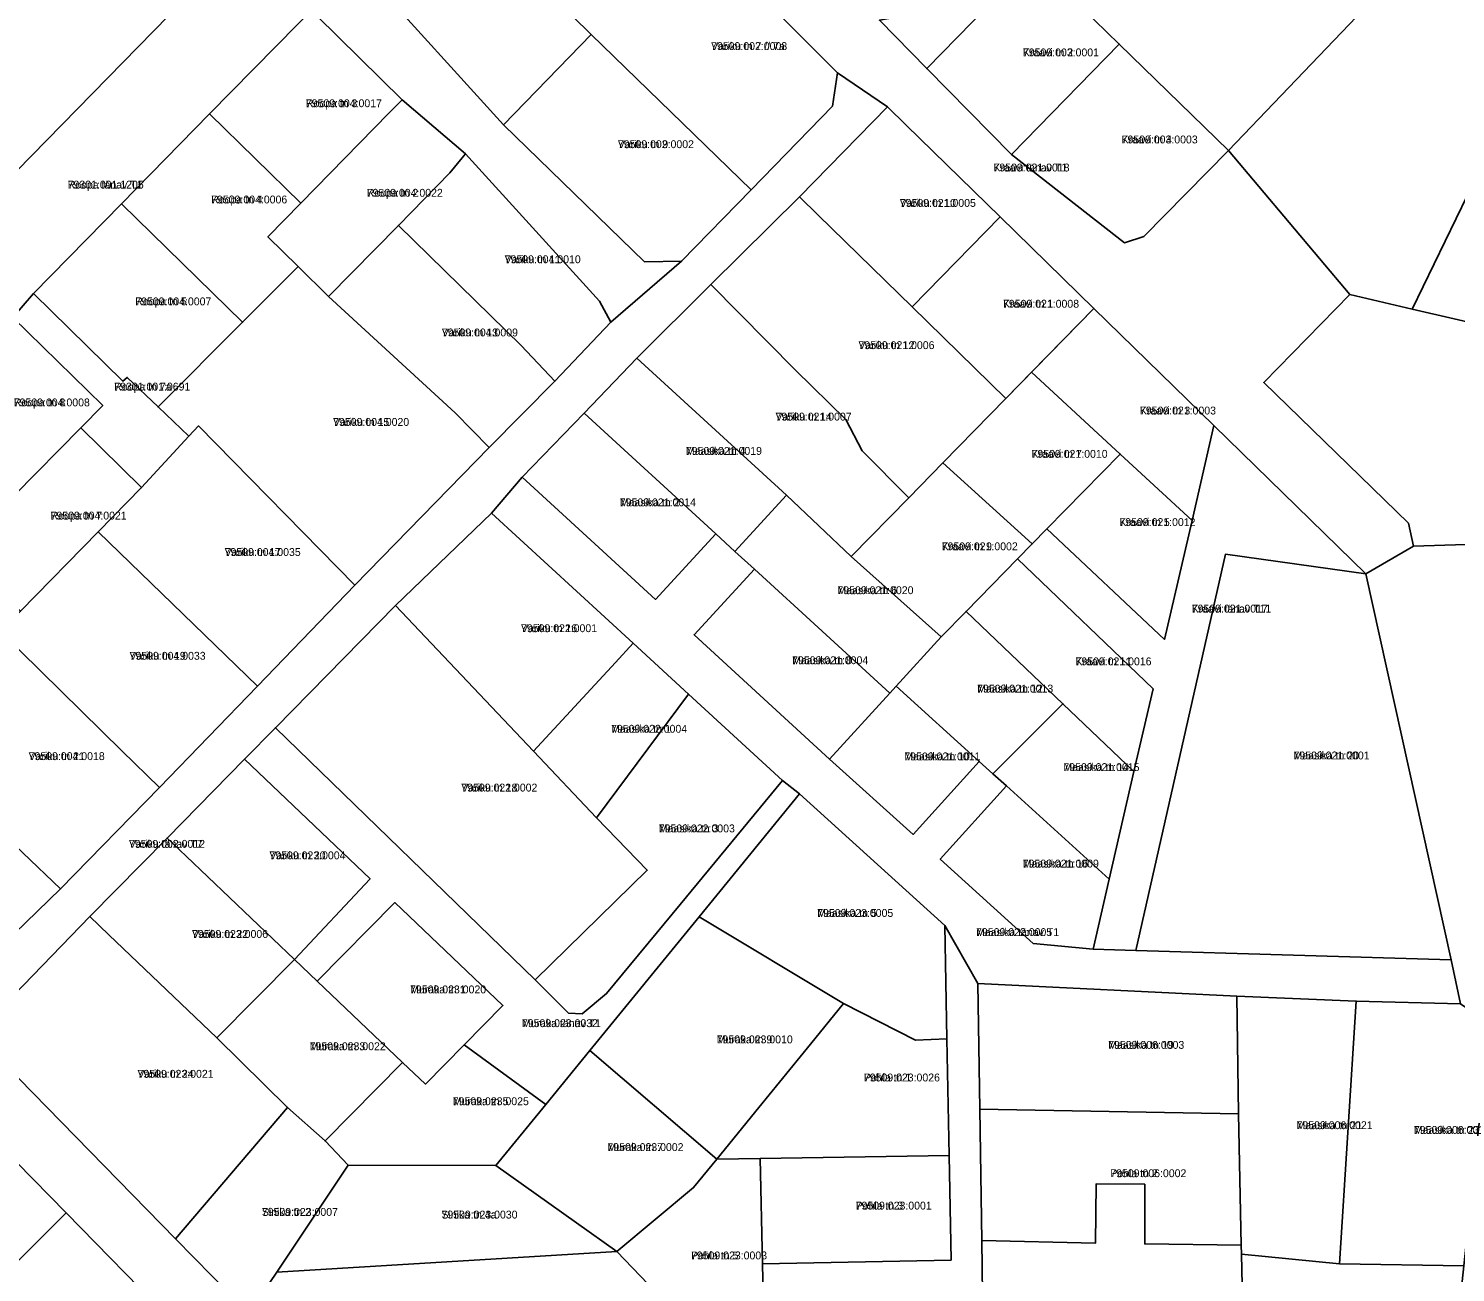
# Model space of a CAD drawing. Extents: x 643847 to 663718, y 6468443 to 6482775.
# Drawn here: x 658434.8 to 658706.9, y 6471070.1 to 6471307.4 of the extents above; entities that cross this region are included whole.
import ezdxf

# ---------------------------------------------------------------- set-up
doc = ezdxf.new("R2010")
doc.units = 0
for name, color, linetype in [('L_AADRESS', 7, 'Continuous'), ('PIIR', 7, 'Continuous'), ('TUNNUS', 7, 'Continuous')]:
    doc.layers.add(name, color=color, linetype=linetype)

msp = doc.modelspace()

# ---------------------------------------------------------------- linework, layer by layer
at = {"layer": 'PIIR'}
for points in [[(658667.9, 6471374.64), (658681.84, 6471388.98), (658712.74, 6471423.15), (658725.04, 6471439.2), (658731.9, 6471452.14), (658803.46, 6471462.91), (658790.44, 6471406.27), (658778.27, 6471410.06), (658762.02, 6471416.49), (658739.98, 6471437.01), (658717.62, 6471414.12), (658680.43, 6471376.08), (658675.68, 6471371.23), (658626.31, 6471320.49), (658606.07, 6471299.73), (658597.05, 6471308.95), (658605.51, 6471310.48), (658620.85, 6471326.25), (658641.07, 6471347.04), (658655.01, 6471361.37)], [(658642.77, 6471304.43), (658626.31, 6471320.49), (658675.68, 6471371.23), (658712.51, 6471335.21), (658663.59, 6471284.1)], [(658712.51, 6471335.21), (658721.8, 6471327.33), (658747.43, 6471319), (658760.36, 6471314.82), (658755.78, 6471292.14), (658727.03, 6471298.7), (658721.72, 6471301.39), (658698.63, 6471253.86), (658686.74, 6471256.66), (658663.59, 6471284.1)], [(658538.52, 6471309.73), (658542.11, 6471306.24), (658525.37, 6471289.04), (658499.62, 6471317.44), (658500.19, 6471323.31), (658512.72, 6471334.81)], [(658588.08, 6471292.56), (658572.57, 6471276.62), (658542.11, 6471306.24), (658538.52, 6471309.73), (658558.17, 6471329.93), (658569.12, 6471318.95), (658589.06, 6471298.96)], [(658626.31, 6471320.49), (658642.77, 6471304.43), (658622.25, 6471283.38), (658606.07, 6471299.73)], [(658705.68, 6471045.12), (658708.5, 6471071.36), (658713.16, 6471114.65), (658711.56, 6471118.9), (658707.89, 6471121.35), (658706.11, 6471129.75), (658689.82, 6471203.36), (658698.88, 6471208.62), (658734.86, 6471209.81), (658743.38, 6471243.53), (658755.78, 6471292.14), (658760.36, 6471314.82), (658765.5, 6471313.17), (658760.7, 6471290.4), (658727.38, 6471132.36), (658718.47, 6471080.15), (658713.7, 6471023.88), (658711.74, 6470952.85), (658701.04, 6470949.42), (658701.84, 6470983.89), (658702.59, 6471016.34)], [(658486.14, 6471308.22), (658487.58, 6471309.69), (658489.77, 6471309.81), (658506.03, 6471293.8), (658503.5, 6471291.21), (658486.71, 6471274.07), (658469.33, 6471291.09)], [(658559.33, 6471263), (658552.26, 6471262.91), (658525.37, 6471289.04), (658542.11, 6471306.24), (658572.57, 6471276.62)], [(658622.25, 6471283.38), (658642.77, 6471304.43), (658663.59, 6471284.1), (658647.49, 6471267.72), (658643.76, 6471266.51)], [(658721.72, 6471301.39), (658727.03, 6471298.7), (658755.78, 6471292.14), (658743.38, 6471243.53), (658698.63, 6471253.86)], [(658518.13, 6471283.46), (658517.5, 6471282.74), (658515.11, 6471279.84), (658505.32, 6471269.84), (658492.02, 6471256.27), (658486.24, 6471261.97), (658480.45, 6471267.68), (658486.71, 6471274.07), (658503.5, 6471291.21), (658506.03, 6471293.8)], [(658598.6, 6471292.43), (658602.17, 6471288.94), (658620.06, 6471271.46), (658603.28, 6471254.3), (658585.4, 6471271.77), (658581.82, 6471275.26)], [(658469.33, 6471291.09), (658486.71, 6471274.07), (658480.45, 6471267.68), (658486.24, 6471261.97), (658475.61, 6471251.35), (658452.52, 6471273.96)], [(658535.16, 6471240.11), (658528.72, 6471246.93), (658505.32, 6471269.84), (658515.11, 6471279.84), (658517.5, 6471282.74), (658518.13, 6471283.46), (658543.68, 6471255.36), (658545.86, 6471251.4)], [(658452.52, 6471273.96), (658475.61, 6471251.35), (658459.49, 6471235.22), (658453.62, 6471240.84), (658452.8, 6471240.1), (658435.71, 6471256.83)], [(658581.82, 6471275.26), (658585.4, 6471271.77), (658603.28, 6471254.3), (658621.17, 6471236.82), (658609.15, 6471224.52), (658602.64, 6471217.88), (658593.75, 6471226.84), (658590.64, 6471232.81), (658581.03, 6471242.22), (658564.93, 6471258.57)], [(658637.94, 6471253.99), (658621.17, 6471236.82), (658603.28, 6471254.3), (658620.06, 6471271.46)], [(658522.64, 6471227.49), (658516.12, 6471234.07), (658492.02, 6471256.27), (658505.32, 6471269.84), (658528.72, 6471246.93), (658535.16, 6471240.11)], [(658497.03, 6471201.22), (658467.19, 6471231.6), (658465.35, 6471229.61), (658459.49, 6471235.22), (658475.61, 6471251.35), (658486.24, 6471261.97), (658492.02, 6471256.27), (658516.12, 6471234.07), (658522.64, 6471227.49)], [(658435.71, 6471256.83), (658452.8, 6471240.1), (658453.62, 6471240.84), (658459.49, 6471235.22), (658465.35, 6471229.61), (658456.35, 6471219.83), (658444.74, 6471231.2), (658448.94, 6471235.48), (658431.78, 6471252.28)], [(658564.93, 6471258.57), (658581.03, 6471242.22), (658590.64, 6471232.81), (658593.75, 6471226.84), (658602.64, 6471217.88), (658591.67, 6471206.65), (658579.32, 6471218.35), (658550.79, 6471244.5)], [(658697.92, 6471213.01), (658670.35, 6471239.87), (658686.74, 6471256.66), (658698.64, 6471253.86), (658743.38, 6471243.53), (658734.86, 6471209.81), (658698.88, 6471208.62)], [(658660.83, 6471231.65), (658656.66, 6471213.56), (658642.98, 6471226.22), (658626.07, 6471241.84), (658637.94, 6471253.99)], [(658431.78, 6471252.28), (658448.94, 6471235.48), (658444.74, 6471231.2), (658432.14, 6471218.35), (658415, 6471235.13)], [(658569.51, 6471207.64), (658565.83, 6471211.02), (658540.75, 6471234.01), (658550.79, 6471244.5), (658579.32, 6471218.35)], [(658626.19, 6471209.07), (658609.15, 6471224.52), (658621.17, 6471236.82), (658626.07, 6471241.84), (658642.98, 6471226.22), (658628.99, 6471211.93)], [(658528.92, 6471221.81), (658540.75, 6471234.01), (658565.83, 6471211.02), (658554.34, 6471198.5)], [(658456.35, 6471219.83), (658448.07, 6471211.37), (658433.26, 6471196.25), (658421.65, 6471207.63), (658432.14, 6471218.35), (658444.74, 6471231.2)], [(658497.03, 6471201.22), (658478.44, 6471181.96), (658448.07, 6471211.37), (658456.35, 6471219.83), (658465.35, 6471229.61), (658467.19, 6471231.6)], [(658645.59, 6471165.65), (658649.23, 6471181.41), (658623.4, 6471206.21), (658626.19, 6471209.07), (658628.99, 6471211.93), (658651.41, 6471190.86), (658656.66, 6471213.56), (658660.83, 6471231.65), (658689.82, 6471203.36), (658663.07, 6471207.15), (658645.94, 6471131.56), (658637.78, 6471131.81), (658640.84, 6471145.11)], [(658623.4, 6471206.21), (658613.59, 6471196.21), (658608.82, 6471191.33), (658591.67, 6471206.65), (658602.64, 6471217.88), (658609.15, 6471224.52), (658626.19, 6471209.07)], [(658651.41, 6471190.86), (658628.99, 6471211.93), (658642.98, 6471226.22), (658656.66, 6471213.56)], [(658550.12, 6471190.14), (658523.09, 6471214.94), (658528.92, 6471221.81), (658554.34, 6471198.5), (658565.83, 6471211.02), (658569.51, 6471207.64), (658573.2, 6471204.28), (658561.72, 6471191.74), (658587.54, 6471168), (658603.47, 6471153.66), (658616.09, 6471167.59), (658618.68, 6471165.25), (658621.27, 6471162.91), (658608.64, 6471148.97), (658626.4, 6471132.88), (658637.78, 6471131.81), (658645.94, 6471131.56), (658706.11, 6471129.75), (658707.89, 6471121.35), (658687.99, 6471121.88), (658665.21, 6471122.79), (658615.84, 6471125.21), (658609.5, 6471136.29), (658581.8, 6471161.41), (658578.58, 6471163.98), (658560.67, 6471180.43)], [(658573.2, 6471204.28), (658569.51, 6471207.64), (658579.32, 6471218.35), (658591.67, 6471206.65), (658608.82, 6471191.33), (658600.25, 6471181.94), (658599.02, 6471180.64)], [(658523.09, 6471214.94), (658550.12, 6471190.14), (658546.73, 6471186.48), (658531.08, 6471169.56), (658504.78, 6471197.35)], [(658459.75, 6471162.61), (658452.61, 6471169.61), (658429.31, 6471192.43), (658433.26, 6471196.25), (658448.07, 6471211.37), (658478.44, 6471181.96)], [(658649.23, 6471181.41), (658645.59, 6471165.65), (658632.04, 6471178.59), (658613.59, 6471196.21), (658623.4, 6471206.21)], [(658645.94, 6471131.56), (658663.07, 6471207.15), (658689.82, 6471203.36), (658706.11, 6471129.75)], [(658561.72, 6471191.74), (658573.2, 6471204.28), (658599.02, 6471180.64), (658587.54, 6471168)], [(658504.78, 6471197.35), (658531.08, 6471169.56), (658543.09, 6471156.85), (658552.78, 6471146.83), (658531.38, 6471125.96), (658481.86, 6471174.01)], [(658616.09, 6471167.59), (658600.25, 6471181.94), (658608.82, 6471191.33), (658613.59, 6471196.21), (658632.04, 6471178.59), (658618.68, 6471165.25)], [(658440.9, 6471143.27), (658433.69, 6471150.16), (658410.17, 6471172.68), (658429.31, 6471192.43), (658452.61, 6471169.61), (658459.75, 6471162.61)], [(658560.67, 6471180.43), (658543.09, 6471156.85), (658531.08, 6471169.56), (658546.73, 6471186.48), (658550.12, 6471190.14)], [(658578.58, 6471163.98), (658559.08, 6471140.31), (658545.03, 6471123.31), (658540.35, 6471119.45), (658537.77, 6471119.57), (658531.38, 6471125.96), (658552.78, 6471146.83), (658543.09, 6471156.85), (658560.67, 6471180.43)], [(658587.54, 6471168), (658599.02, 6471180.64), (658600.25, 6471181.94), (658616.09, 6471167.59), (658603.47, 6471153.66)], [(658640.84, 6471145.11), (658621.27, 6471162.91), (658618.68, 6471165.25), (658632.04, 6471178.59), (658645.59, 6471165.65)], [(658416.27, 6471133.08), (658389.69, 6471159.47), (658406.6, 6471176.18), (658410.17, 6471172.68), (658433.69, 6471150.16), (658440.9, 6471143.27), (658423.21, 6471126.19)], [(658525.26, 6471121.01), (658504.63, 6471140.68), (658489.85, 6471125.7), (658485.5, 6471129.84), (658499.92, 6471145.18), (658475.97, 6471168.02), (658481.86, 6471174.01), (658531.38, 6471125.96), (658537.77, 6471119.57), (658540.35, 6471119.45), (658545.03, 6471123.31), (658559.08, 6471140.31), (658578.58, 6471163.98), (658581.8, 6471161.41), (658562.66, 6471137.96), (658541.82, 6471112.44), (658533.41, 6471102.13), (658517.88, 6471113.53)], [(658475.97, 6471168.02), (658499.92, 6471145.18), (658485.5, 6471129.84), (658464.87, 6471149.51), (658461.2, 6471152.98)], [(658609.5, 6471136.29), (658609.91, 6471114.69), (658603.92, 6471114.46), (658590.22, 6471121.4), (658562.66, 6471137.96), (658581.8, 6471161.41)], [(658626.4, 6471132.88), (658608.64, 6471148.97), (658621.27, 6471162.91), (658640.84, 6471145.11), (658637.78, 6471131.81)], [(658461.2, 6471152.98), (658464.87, 6471149.51), (658485.5, 6471129.84), (658470.72, 6471114.88), (658450.09, 6471134.54), (658446.47, 6471137.99)], [(658504.63, 6471140.68), (658525.26, 6471121.01), (658517.88, 6471113.53), (658510.48, 6471106.04), (658506.13, 6471110.18), (658489.85, 6471125.7)], [(658446.47, 6471137.99), (658450.09, 6471134.54), (658470.72, 6471114.88), (658484.2, 6471101.6), (658462.81, 6471076.54), (658424.66, 6471115.49)], [(658562.66, 6471137.96), (658590.22, 6471121.4), (658583.9, 6471113.65), (658574.04, 6471101.56), (658566.02, 6471091.72), (658541.82, 6471112.44)], [(658485.5, 6471129.84), (658489.85, 6471125.7), (658506.13, 6471110.18), (658491.33, 6471095.2), (658484.2, 6471101.6), (658470.72, 6471114.88)], [(658615.84, 6471125.21), (658665.21, 6471122.79), (658665.52, 6471100.35), (658616.19, 6471101.24)], [(658610.34, 6471092.46), (658574.29, 6471091.85), (658566.02, 6471091.72), (658574.04, 6471101.56), (658583.9, 6471113.65), (658590.22, 6471121.4), (658603.92, 6471114.46), (658609.91, 6471114.69)], [(658665.21, 6471122.79), (658687.99, 6471121.88), (658684.81, 6471071.8), (658666.09, 6471073.61), (658666.06, 6471075.36), (658665.52, 6471100.35)], [(658707.89, 6471121.35), (658711.56, 6471118.9), (658713.16, 6471114.65), (658708.5, 6471071.36), (658684.81, 6471071.8), (658687.99, 6471121.88)], [(658461.6, 6471061.42), (658441.96, 6471081.48), (658416.68, 6471107.25), (658424.66, 6471115.49), (658462.81, 6471076.54), (658476.83, 6471062.32), (658517.42, 6471018.28), (658559.1, 6470978.87), (658559.41, 6470962.42), (658559.54, 6470955.69), (658559.82, 6470941.57), (658546.56, 6470940.85), (658544.36, 6470976.37), (658531.54, 6470989.71), (658510.64, 6471011.43), (658468.62, 6471054.26), (658441.51, 6471027.68), (658414.39, 6471001.08), (658383.69, 6470970.97), (658376.94, 6470978.53), (658388.98, 6470990.32), (658401.04, 6471002.12), (658427.31, 6471027.85), (658444.46, 6471044.63)], [(658506.13, 6471110.18), (658510.48, 6471106.04), (658517.88, 6471113.53), (658533.41, 6471102.13), (658523.92, 6471090.52), (658495.76, 6471090.6), (658491.33, 6471095.2)], [(658533.41, 6471102.13), (658541.82, 6471112.44), (658566.02, 6471091.72), (658561.6, 6471086.3), (658546.99, 6471074.11), (658523.92, 6471090.52)], [(658441.96, 6471081.48), (658424.96, 6471064.55), (658398.88, 6471089.29), (658416.68, 6471107.25)], [(658462.81, 6471076.54), (658484.2, 6471101.6), (658491.33, 6471095.2), (658495.76, 6471090.6), (658482.11, 6471070.21), (658476.83, 6471062.32)], [(658647.66, 6471075.58), (658647.66, 6471086.94), (658638.37, 6471087.02), (658638.26, 6471075.74), (658616.56, 6471076.24), (658616.19, 6471101.24), (658665.52, 6471100.35), (658666.06, 6471075.36)], [(658495.76, 6471090.6), (658523.92, 6471090.52), (658546.99, 6471074.11), (658482.11, 6471070.21)], [(658574.86, 6471065.78), (658575.24, 6471044.59), (658546.99, 6471074.11), (658561.6, 6471086.3), (658566.02, 6471091.72), (658574.29, 6471091.85), (658574.73, 6471071.78)], [(658610.72, 6471072.47), (658574.73, 6471071.78), (658574.29, 6471091.85), (658610.34, 6471092.46)], [(658616.56, 6471076.24), (658638.26, 6471075.74), (658638.37, 6471087.02), (658647.66, 6471086.94), (658647.66, 6471075.58), (658666.06, 6471075.36), (658666.09, 6471073.61), (658666.6, 6471049.89), (658616.93, 6471050.49)], [(658461.6, 6471061.42), (658444.46, 6471044.63), (658424.96, 6471064.55), (658441.96, 6471081.48)], [(658476.83, 6471062.32), (658482.11, 6471070.21), (658546.99, 6471074.11), (658575.24, 6471044.59), (658520.37, 6471043.98), (658521.38, 6471022.46), (658517.42, 6471018.28)], [(658705.68, 6471045.12), (658702.25, 6471045.09), (658666.72, 6471044.69), (658666.6, 6471049.89), (658666.09, 6471073.61), (658684.81, 6471071.8), (658708.5, 6471071.36)]]:
    msp.add_lwpolyline(points, close=True, dxfattribs=at)
for points in [[(658007.99, 6470900.13), (658096.06, 6470989.93), (658200.31, 6471096.15), (658280.05, 6471177.4), (658347.18, 6471246.04), (658408.18, 6471307.67), (658438.67, 6471334.7), (658478.11, 6471367.3), (658546.87, 6471437.66), (658591.46, 6471443.7), (658580.57, 6471432.42), (658519.5, 6471369.2), (658377.32, 6471223.85), (658309.25, 6471156.22), (658235.32, 6471080.84), (658070.5, 6470912.78)], [(658377.32, 6471223.85), (658519.5, 6471369.2)], [(658597.05, 6471308.95), (658606.07, 6471299.73), (658622.25, 6471283.38), (658643.76, 6471266.51), (658647.49, 6471267.72), (658663.59, 6471284.1), (658686.74, 6471256.66), (658670.35, 6471239.87), (658697.92, 6471213.01), (658698.88, 6471208.62), (658689.82, 6471203.36), (658660.83, 6471231.65), (658637.94, 6471253.99), (658620.06, 6471271.46), (658602.17, 6471288.94), (658598.6, 6471292.43), (658589.06, 6471298.96), (658569.12, 6471318.95)], [(658499.62, 6471317.44), (658525.37, 6471289.04), (658552.26, 6471262.91), (658559.33, 6471263), (658545.86, 6471251.4), (658543.68, 6471255.36), (658518.13, 6471283.46), (658506.03, 6471293.8), (658489.77, 6471309.81)], [(658486.14, 6471308.22), (658469.33, 6471291.09), (658452.52, 6471273.96), (658435.71, 6471256.83), (658431.78, 6471252.28)], [(658423.21, 6471126.19), (658440.9, 6471143.27), (658459.75, 6471162.61), (658478.44, 6471181.96), (658497.03, 6471201.22), (658522.64, 6471227.49), (658535.16, 6471240.11), (658545.86, 6471251.4), (658559.33, 6471263), (658572.57, 6471276.62), (658588.08, 6471292.56), (658589.06, 6471298.96), (658598.6, 6471292.43), (658581.82, 6471275.26), (658564.93, 6471258.57), (658550.79, 6471244.5), (658540.75, 6471234.01), (658528.92, 6471221.81), (658523.09, 6471214.94), (658504.78, 6471197.35), (658481.86, 6471174.01), (658475.97, 6471168.02), (658461.2, 6471152.98), (658446.47, 6471137.99), (658424.66, 6471115.49)], [(658574.86, 6471065.78), (658574.73, 6471071.78), (658610.72, 6471072.47), (658610.34, 6471092.46), (658609.91, 6471114.69), (658609.5, 6471136.29), (658615.84, 6471125.21), (658616.19, 6471101.24), (658616.56, 6471076.24), (658616.93, 6471050.49)]]:
    msp.add_lwpolyline(points, dxfattribs=at)

# ---------------------------------------------------------------- texts
at = {"layer": 'L_AADRESS'}
for s, p in [('Variku tn 7 // 7a', (658564.96, 6471303.28)), ('Kraavi tn 2', (658624.42, 6471302.08)), ('Roopa tn 3', (658487.68, 6471292.38)), ('Kraavi tn 4', (658643.24, 6471285.47)), ('Variku tn 9', (658547.18, 6471284.57)), ('Kraavi tänav T1', (658618.8, 6471280.12)), ('Roopa tänav T1', (658442.25, 6471276.86)), ('Roopa tn 4', (658469.62, 6471274.02)), ('Roopa tn 2', (658499.29, 6471275.3)), ('Variku tn 10', (658600.94, 6471273.37)), ('Variku tn 11', (658525.59, 6471262.62)), ('Roopa tn 5', (658455.15, 6471254.59)), ('Kraavi tn 1', (658620.62, 6471254.14)), ('Variku tn 13', (658513.61, 6471248.66)), ('Variku tn 12', (658593.05, 6471246.24)), ('Roopa tn 7a', (658451.14, 6471238.33)), ('Roopa tn 8', (658431.98, 6471235.32)), ('Kraavi tn 3', (658646.73, 6471233.77)), ('Variku tn 15', (658492.88, 6471231.59)), ('Variku tn 14', (658577.25, 6471232.61)), ('Maasika tn 4', (658560.15, 6471226.07)), ('Kraavi tn 7', (658626.06, 6471225.51)), ('Maasika tn 2', (658547.55, 6471216.26)), ('Roopa tn 7', (658439, 6471213.73)), ('Kraavi tn 5', (658642.82, 6471212.49)), ('Variku tn 17', (658472.19, 6471206.78)), ('Kraavi tn 9', (658608.93, 6471207.87)), ('Maasika tn 6', (658589.05, 6471199.5)), ('Kraavi tänav T11', (658656.61, 6471195.99)), ('Variku tn 16', (658528.71, 6471192.25)), ('Variku tn 19', (658454.06, 6471186.99)), ('Maasika tn 8', (658580.41, 6471186.14)), ('Kraavi tn 11', (658634.44, 6471185.93)), ('Maasika tn 12', (658615.69, 6471180.73)), ('Maasika tn 1', (658545.88, 6471173.07)), ('Variku tn 21', (658434.81, 6471167.85)), ('Maasika tn 10', (658601.81, 6471167.8)), ('Maasika tn 20', (658676.02, 6471167.98)), ('Maasika tn 14', (658632.14, 6471165.76)), ('Variku tn 18', (658517.32, 6471161.85)), ('Maasika tn 3', (658554.98, 6471154.07)), ('Variku tänav T7', (658453.94, 6471151.12)), ('Variku tn 20', (658480.73, 6471148.93)), ('Maasika tn 16', (658624.39, 6471147.36)), ('Maasika tn 5', (658585.19, 6471137.94)), ('Variku tn 22', (658465.97, 6471133.93)), ('Maasika tänav T1', (658615.49, 6471134.29)), ('Muraka tn 1', (658507.55, 6471123.36)), ('Muraka tänav T1', (658528.88, 6471116.92)), ('Muraka tn 9', (658566.02, 6471113.83)), ('Muraka tn 3', (658488.4, 6471112.52)), ('Maasika tn 19', (658640.68, 6471112.78)), ('Variku tn 24', (658455.58, 6471107.26)), ('Pohla tn 1', (658594.09, 6471106.56)), ('Muraka tn 5', (658515.7, 6471102.03)), ('Maasika tn 21', (658676.6, 6471097.46)), ('Maasika tn 23', (658698.98, 6471096.56)), ('Muraka tn 7', (658545.19, 6471093.28)), ('Pohla tn 2', (658641.08, 6471088.3)), ('Sinika tn 2', (658479.29, 6471080.92)), ('Pohla tn 3', (658592.52, 6471082.12)), ('Sinika tn 4a', (658513.54, 6471080.41)), ('Pohla tn 5', (658561.12, 6471072.62))]:
    msp.add_text(s, height=1.5, dxfattribs=at).set_placement(p)
at = {"layer": 'TUNNUS'}
for s, p in [('79509:002:0008', (658564.96, 6471303.28)), ('79509:003:0001', (658624.42, 6471302.08)), ('79509:004:0017', (658487.68, 6471292.38)), ('79509:003:0003', (658643.24, 6471285.47)), ('79509:002:0002', (658547.18, 6471284.57)), ('79509:021:0018', (658618.8, 6471280.12)), ('79301:001:1205', (658442.25, 6471276.86)), ('79509:004:0006', (658469.62, 6471274.02)), ('79509:004:0022', (658499.29, 6471275.3)), ('79509:021:0005', (658600.94, 6471273.37)), ('79509:004:0010', (658525.59, 6471262.62)), ('79509:004:0007', (658455.15, 6471254.59)), ('79509:021:0008', (658620.62, 6471254.14)), ('79509:004:0009', (658513.61, 6471248.66)), ('79509:021:0006', (658593.05, 6471246.24)), ('79301:001:0691', (658451.14, 6471238.33)), ('79509:004:0008', (658431.98, 6471235.32)), ('79509:021:0003', (658646.73, 6471233.77)), ('79509:004:0020', (658492.88, 6471231.59)), ('79509:021:0007', (658577.25, 6471232.61)), ('79509:021:0019', (658560.15, 6471226.07)), ('79509:021:0010', (658626.06, 6471225.51)), ('79509:021:0014', (658547.55, 6471216.26)), ('79509:004:0021', (658439, 6471213.73)), ('79509:021:0012', (658642.82, 6471212.49)), ('79509:004:0035', (658472.19, 6471206.78)), ('79509:021:0002', (658608.93, 6471207.87)), ('79509:021:0020', (658589.05, 6471199.5)), ('79509:021:0017', (658656.61, 6471195.99)), ('79509:022:0001', (658528.71, 6471192.25)), ('79509:004:0033', (658454.06, 6471186.99)), ('79509:021:0004', (658580.41, 6471186.14)), ('79509:021:0016', (658634.44, 6471185.93)), ('79509:021:0013', (658615.69, 6471180.73)), ('79509:022:0004', (658545.88, 6471173.07)), ('79509:004:0018', (658434.81, 6471167.85)), ('79509:021:0011', (658601.81, 6471167.8)), ('79509:021:0001', (658676.02, 6471167.98)), ('79509:021:0015', (658632.14, 6471165.76)), ('79509:022:0002', (658517.32, 6471161.85)), ('79509:022:0003', (658554.98, 6471154.07)), ('79509:002:0012', (658453.94, 6471151.12)), ('79509:023:0004', (658480.73, 6471148.93)), ('79509:021:0009', (658624.39, 6471147.36)), ('79509:023:0005', (658585.19, 6471137.94)), ('79509:023:0006', (658465.97, 6471133.93)), ('79509:022:0005', (658615.49, 6471134.29)), ('79509:023:0020', (658507.55, 6471123.36)), ('79509:023:0032', (658528.88, 6471116.92)), ('79509:023:0010', (658566.02, 6471113.83)), ('79509:023:0022', (658488.4, 6471112.52)), ('79509:006:0003', (658640.68, 6471112.78)), ('79509:023:0021', (658455.58, 6471107.26)), ('79509:023:0026', (658594.09, 6471106.56)), ('79509:023:0025', (658515.7, 6471102.03)), ('79509:006:0021', (658676.6, 6471097.46)), ('79509:006:0018', (658698.98, 6471096.56)), ('79509:023:0002', (658545.19, 6471093.28)), ('79509:006:0002', (658641.08, 6471088.3)), ('79509:023:0007', (658479.29, 6471080.92)), ('79509:023:0001', (658592.52, 6471082.12)), ('79509:023:0030', (658513.54, 6471080.41)), ('79509:023:0003', (658561.12, 6471072.62))]:
    msp.add_text(s, height=1.5, dxfattribs=at).set_placement(p)

doc.saveas('drawing.dxf')
